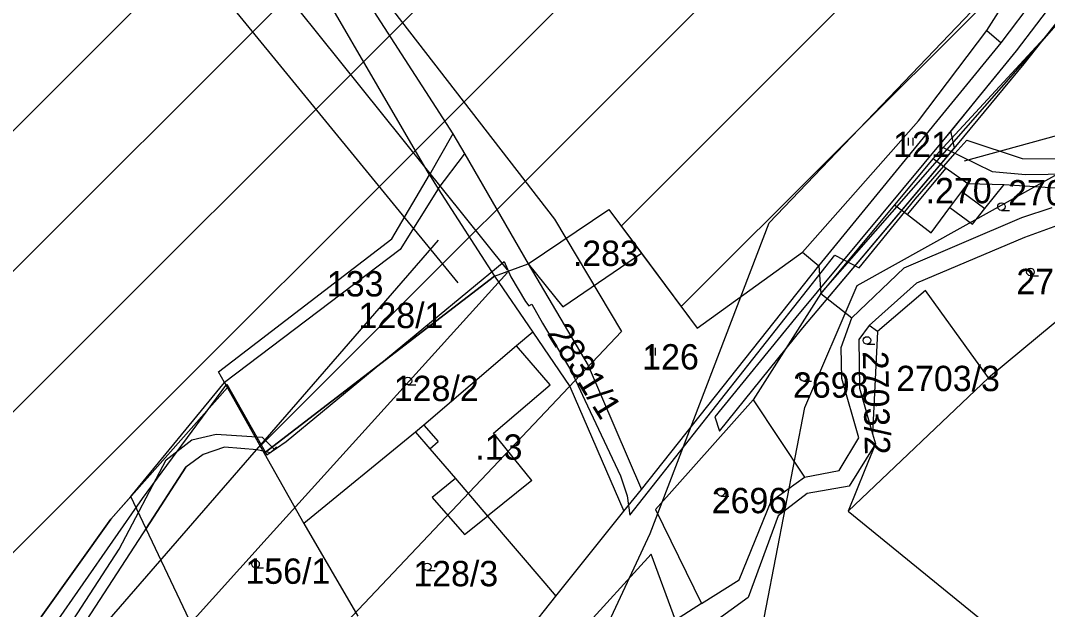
# Model space of a CAD drawing. Extents: x -564810 to -550519, y -1045831 to -1034011.
# Drawn here: x -552633.3 to -552426.8, y -1036239 to -1036120.6 of the extents above; entities that cross this region are included whole.
import ezdxf

# ---------------------------------------------------------------- set-up
doc = ezdxf.new("R2010")
doc.units = 0
for name, color, linetype in [('KN stav', 7, 'Continuous'), ('Obvod KPU', 7, 'Continuous'), ('Odvodněné plochy', 7, 'Continuous'), ('Parcelní čísla', 7, 'Continuous'), ('Polní cesty stavající', 7, 'Continuous'), ('přeložka st silnice', 7, 'Continuous'), ('STG', 7, 'Continuous'), ('Vedení VN', 7, 'Continuous'), ('vodní toky', 7, 'Continuous'), ('Vrstva 22', 7, 'Continuous'), ('Vrstva 33', 7, 'Continuous'), ('Vrstva 39', 7, 'Continuous'), ('Vrstva 4', 7, 'Continuous'), ('zamokř ploch', 7, 'Continuous')]:
    doc.layers.add(name, color=color, linetype=linetype)

msp = doc.modelspace()

# ---------------------------------------------------------------- linework, layer by layer
at = {"layer": 'KN stav'}
for p, q in [((-552439.04, -1036122.55), (-552415.84, -1036086.02)), ((-552436.15, -1036125.06), (-552407.92, -1036087.53)), ((-552551.05, -1036151.62), (-552585.7, -1036092.11)), ((-552562.25, -1036118.76), (-552546.35, -1036143.32)), ((-552425.11, -1036121.49), (-552447.79, -1036146.11)), ((-552452.79, -1036140.7), (-552439.04, -1036122.55)), ((-552439.04, -1036122.55), (-552436.15, -1036125.06)), ((-552472.81, -1036169.88), (-552436.15, -1036125.06)), ((-552476.07, -1036167.13), (-552452.79, -1036140.7)), ((-552546.35, -1036143.32), (-552551.05, -1036151.62)), ((-552546.35, -1036143.32), (-552543.98, -1036147.4)), ((-552447.79, -1036146.11), (-552449.83, -1036148.33)), ((-552447.79, -1036146.11), (-552437.97, -1036150.94)), ((-552543.98, -1036147.4), (-552531.19, -1036169.47)), ((-552449.83, -1036148.33), (-552457.56, -1036157.6)), ((-552449.83, -1036148.33), (-552447.18, -1036150.22)), ((-552447.18, -1036150.22), (-552442.87, -1036153.3)), ((-552558.64, -1036164.45), (-552551.05, -1036151.62)), ((-552551.05, -1036151.62), (-552549.34, -1036154.4)), ((-552437.97, -1036150.94), (-552431.25, -1036151.53)), ((-552431.25, -1036151.53), (-552397.93, -1036151.01)), ((-552549.34, -1036154.4), (-552556.92, -1036166.59)), ((-552549.34, -1036154.4), (-552537.97, -1036171.97)), ((-552442.87, -1036153.3), (-552435.51, -1036153.55)), ((-552439.4, -1036158.36), (-552435.51, -1036153.55)), ((-552435.51, -1036153.55), (-552414.02, -1036154.88)), ((-552531.19, -1036169.47), (-552514.99, -1036158.56)), ((-552514.99, -1036158.56), (-552508.46, -1036167.33)), ((-552457.56, -1036157.6), (-552472.42, -1036175.42)), ((-552457.56, -1036157.6), (-552454.98, -1036159.58)), ((-552450.2, -1036163.24), (-552446.44, -1036158.14)), ((-552446.44, -1036158.14), (-552441.92, -1036161.48)), ((-552441.92, -1036161.48), (-552439.4, -1036158.36)), ((-552431.96, -1036160.17), (-552425.89, -1036158.17)), ((-552455.66, -1036170.26), (-552431.96, -1036160.17)), ((-552454.98, -1036159.58), (-552450.2, -1036163.24)), ((-552424.82, -1036161.75), (-552431.48, -1036164.21)), ((-552593.47, -1036191.23), (-552558.64, -1036164.45)), ((-552431.48, -1036164.21), (-552453.15, -1036173.35)), ((-552556.92, -1036166.59), (-552592.25, -1036193.36)), ((-552524.26, -1036178.11), (-552508.46, -1036167.33)), ((-552508.46, -1036167.33), (-552497.23, -1036182.42)), ((-552497.23, -1036182.42), (-552476.07, -1036167.13)), ((-552476.07, -1036167.13), (-552472.81, -1036169.88)), ((-552531.19, -1036169.47), (-552519.16, -1036189.93)), ((-552531.19, -1036169.47), (-552524.26, -1036178.11)), ((-552508.44, -1036214.84), (-552472.81, -1036169.88)), ((-552466.14, -1036180.32), (-552455.66, -1036170.26)), ((-552537.97, -1036171.97), (-552584.28, -1036207.54)), ((-552537.97, -1036171.97), (-552530.3, -1036183.21)), ((-552453.15, -1036173.35), (-552462.67, -1036181.91)), ((-552472.42, -1036175.42), (-552485.97, -1036196.86)), ((-552472.42, -1036175.42), (-552466.14, -1036180.32)), ((-552451.34, -1036174.84), (-552460.98, -1036183.1)), ((-552440.44, -1036189.97), (-552451.34, -1036174.84)), ((-552418.79, -1036175.85), (-552438.69, -1036192.39)), ((-552468.32, -1036186.28), (-552466.14, -1036180.32)), ((-552530.3, -1036183.21), (-552533.54, -1036185.98)), ((-552530.3, -1036183.21), (-552522.86, -1036194.13)), ((-552462.67, -1036181.91), (-552464.76, -1036184.7)), ((-552460.98, -1036183.1), (-552462.67, -1036181.91)), ((-552460.98, -1036183.1), (-552461.99, -1036203.69)), ((-552533.54, -1036185.98), (-552552.17, -1036201.9)), ((-552464.76, -1036184.7), (-552464.61, -1036194.49)), ((-552468.18, -1036192.53), (-552468.32, -1036186.28)), ((-552519.16, -1036189.93), (-552508.44, -1036214.84)), ((-552438.69, -1036192.39), (-552440.44, -1036189.97)), ((-552592.25, -1036193.36), (-552593.47, -1036191.23)), ((-552611.08, -1036216.27), (-552592.25, -1036193.36)), ((-552592.25, -1036193.36), (-552584.28, -1036207.54)), ((-552522.86, -1036194.13), (-552511.96, -1036219.23)), ((-552464.76, -1036204.45), (-552468.18, -1036192.53)), ((-552438.69, -1036192.39), (-552466.93, -1036219.2)), ((-552464.61, -1036194.49), (-552461.99, -1036203.69)), ((-552485.97, -1036196.86), (-552505.62, -1036218.86)), ((-552485.97, -1036196.86), (-552475.68, -1036212.41)), ((-552552.17, -1036201.9), (-552553.84, -1036203.33)), ((-552553.84, -1036203.33), (-552576.32, -1036221.71)), ((-552553.84, -1036203.33), (-552550.99, -1036206.66)), ((-552468.69, -1036211.06), (-552464.76, -1036204.45)), ((-552461.99, -1036203.69), (-552461.43, -1036205.67)), ((-552550.99, -1036206.66), (-552545.84, -1036212.69)), ((-552461.43, -1036205.67), (-552466.68, -1036214.23)), ((-552461.43, -1036205.67), (-552463.55, -1036210.9)), ((-552584.28, -1036207.54), (-552576.32, -1036221.71)), ((-552545.84, -1036212.69), (-552550.5, -1036216.47)), ((-552482.37, -1036217.21), (-552475.68, -1036212.41)), ((-552475.68, -1036212.41), (-552468.69, -1036211.06)), ((-552463.55, -1036210.9), (-552466.93, -1036219.2)), ((-552511.96, -1036219.23), (-552508.44, -1036214.84)), ((-552466.68, -1036214.23), (-552475.14, -1036215.66)), ((-552611.08, -1036216.27), (-552615.12, -1036220.82)), ((-552591.56, -1036257.34), (-552611.08, -1036216.27)), ((-552550.5, -1036216.47), (-552544, -1036223.91)), ((-552475.14, -1036215.66), (-552480.94, -1036220.19)), ((-552505.62, -1036218.86), (-552496.35, -1036237.82)), ((-552488.78, -1036233.07), (-552482.37, -1036217.21)), ((-552615.12, -1036220.82), (-552629.11, -1036240.48)), ((-552544, -1036223.91), (-552539.4, -1036220.23)), ((-552539.4, -1036220.23), (-552527.88, -1036233.7)), ((-552525.64, -1036236.32), (-552511.96, -1036219.23)), ((-552480.94, -1036220.19), (-552486.98, -1036236.6)), ((-552466.93, -1036219.2), (-552429.76, -1036249.45)), ((-552576.32, -1036221.71), (-552565.44, -1036240.35)), ((-552506.51, -1036227.86), (-552529.69, -1036253.28)), ((-552501.62, -1036241.13), (-552506.51, -1036227.86)), ((-552496.35, -1036237.82), (-552488.78, -1036233.07)), ((-552527.88, -1036233.7), (-552525.64, -1036236.32)), ((-552549.35, -1036265.95), (-552525.64, -1036236.32)), ((-552486.98, -1036236.6), (-552493.81, -1036241.52)), ((-552496.35, -1036237.82), (-552501.62, -1036241.13))]:
    msp.add_line(p, q, dxfattribs=at)
at = {"layer": 'Obvod KPU'}
for p, q in [((-552445.46, -1036147.32), (-552443.06, -1036144.59)), ((-552443.06, -1036144.59), (-552431.9, -1036148.29)), ((-552453.42, -1036156.47), (-552445.46, -1036147.32)), ((-552431.9, -1036148.29), (-552396.09, -1036148.48)), ((-552464.67, -1036170.27), (-552453.42, -1036156.47)), ((-552579.83, -1036205.24), (-552536.04, -1036169.05)), ((-552536.04, -1036169.05), (-552534.69, -1036172.12)), ((-552510.78, -1036220), (-552469.56, -1036167.77)), ((-552469.56, -1036167.77), (-552464.67, -1036170.27)), ((-552534.69, -1036172.12), (-552531.73, -1036177.04)), ((-552531.73, -1036177.04), (-552531.1, -1036177.95)), ((-552531.1, -1036177.95), (-552530.49, -1036177.63)), ((-552530.49, -1036177.63), (-552528.35, -1036181.39)), ((-552528.35, -1036181.39), (-552522.51, -1036191.11)), ((-552522.51, -1036191.11), (-552519.84, -1036196.9)), ((-552608.73, -1036216.69), (-552591.76, -1036193.67)), ((-552591.76, -1036193.67), (-552583.76, -1036207.89)), ((-552519.84, -1036196.9), (-552512.64, -1036212.09)), ((-552583.76, -1036207.89), (-552579.83, -1036205.24)), ((-552512.64, -1036212.09), (-552511.33, -1036216.12)), ((-552626.64, -1036242.39), (-552608.73, -1036216.69)), ((-552511.33, -1036216.12), (-552510.78, -1036220))]:
    msp.add_line(p, q, dxfattribs=at)
at = {"layer": 'Odvodněné plochy'}
msp.add_lwpolyline([(-552771.59, -1036406.86), (-552722.24, -1036373.97), (-552691.61, -1036352.2), (-552668.59, -1036323.19), (-552652.27, -1036296.92), (-552629.11, -1036240.48), (-552615.12, -1036220.82), (-552615.12, -1036220.82), (-552591.66, -1036194.39), (-552584.28, -1036207.54), (-552537.97, -1036171.97), (-552531.19, -1036169.47), (-552514.99, -1036158.56), (-552497.23, -1036182.42), (-552476.07, -1036167.13), (-552472.81, -1036169.88), (-552472.42, -1036175.42), (-552425.11, -1036121.49)], dxfattribs=at)
at = {"layer": 'Polní cesty stavající'}
for p, q in [((-552421.46, -1036111.27), (-552433.1, -1036126.65)), ((-552431.52, -1036129.27), (-552418.1, -1036112.21)), ((-552433.1, -1036126.65), (-552440.88, -1036136.16)), ((-552444.95, -1036145.48), (-552431.52, -1036129.27)), ((-552440.89, -1036136.18), (-552446.29, -1036142.78)), ((-552440.87, -1036136.17), (-552440.89, -1036136.18)), ((-552440.88, -1036136.16), (-552440.87, -1036136.17)), ((-552447.39, -1036144.13), (-552477.41, -1036180.25)), ((-552446.29, -1036142.78), (-552447.39, -1036144.13)), ((-552445.55, -1036146.19), (-552446.29, -1036142.78)), ((-552476.03, -1036182.36), (-552445.55, -1036146.19)), ((-552445.55, -1036146.19), (-552444.95, -1036145.48)), ((-552445.55, -1036146.19), (-552445.55, -1036146.19)), ((-552477.41, -1036180.25), (-552493.69, -1036200.28)), ((-552492.77, -1036203.16), (-552476.03, -1036182.36)), ((-552493.69, -1036200.28), (-552492.77, -1036203.16))]:
    msp.add_line(p, q, dxfattribs=at)
at = {"layer": 'přeložka st silnice'}
for p, q in [((-553001.93, -1036509.87), (-552464.8, -1035972.74)), ((-552965.98, -1036502.2), (-552453.83, -1035990.05)), ((-552923.8, -1036488.3), (-552442.99, -1036007.49)), ((-552868.08, -1036460.87), (-552432.14, -1036024.93)), ((-552585.07, -1036206.14), (-552421.3, -1036042.38)), ((-552512.52, -1036161.88), (-552410.46, -1036059.82)), ((-552500.45, -1036178.09), (-552399.61, -1036077.26))]:
    msp.add_line(p, q, dxfattribs=at)
at = {"layer": 'STG'}
msp.add_lwpolyline([(-553913.89, -1037214.19), (-553796.31, -1037140.69), (-553706.3, -1037067.18), (-553629.14, -1036991.84), (-553566.68, -1036914.66), (-553476.66, -1036833.81), (-553318.67, -1036752.96), (-553234.16, -1036692.32), (-553142.31, -1036650.05), (-553048.61, -1036626.16), (-552953.09, -1036624.32), (-552903.48, -1036624.32), (-552861.23, -1036602.27), (-552798.77, -1036576.55), (-552738.15, -1036530.61), (-552646.29, -1036431.38), (-552581.99, -1036368.9), (-552545.25, -1036306.42), (-552506.67, -1036223.73), (-552482.79, -1036161.25), (-552440.54, -1036117.15)], dxfattribs=at)
at = {"layer": 'Vedení VN'}
msp.add_line((-552397.31, -1036136.11), (-552443.59, -1036148.81), dxfattribs=at)
for points in [[(-553567.53, -1034875.85), (-552617.75, -1036041.77), (-552525.91, -1036160.49), (-552512.48, -1036183.11), (-552698.29, -1036379.56), (-552912.35, -1036500.4), (-553117.93, -1036544.92), (-553344, -1036644.56), (-553507.2, -1036737.84), (-553648.49, -1036896.84), (-553694.41, -1037244.51), (-553658.38, -1037334.97)], [(-552545.26, -1036173.28), (-552777.69, -1035889.21), (-553252.44, -1035311.15), (-553606.39, -1034885.74)], [(-552535.38, -1036170.7), (-552615.17, -1036071.15), (-552694.28, -1035972.71), (-552775.29, -1035871.78), (-552858.09, -1035768.77), (-552941.67, -1035664.72), (-552998.64, -1035594.13), (-553079.78, -1035497.35), (-553163.27, -1035397.16), (-553257.3, -1035282.84), (-553335.17, -1035188.27), (-553563.62, -1034910.91)], [(-553684.52, -1037352.63), (-553725.5, -1037238.15), (-553666.15, -1036855.85), (-553493.77, -1036691.9), (-553319.98, -1036604.98), (-553120.76, -1036515.94), (-552942.02, -1036478.49), (-552709.59, -1036345.64), (-552689.1, -1036325.85), (-552549.22, -1036164.73)], [(-552535.38, -1036171.2), (-552583.65, -1036224.68), (-552638.09, -1036285.01), (-552707.08, -1036361.35), (-552775.22, -1036401.6), (-552849.05, -1036445.27), (-552919.03, -1036487.18), (-553014.59, -1036507.93)]]:
    msp.add_lwpolyline(points, dxfattribs=at)
at = {"layer": 'vodní toky'}
for p, q in [((-552598.82, -1036204.89), (-552593.95, -1036203.74)), ((-552593.95, -1036203.74), (-552584.68, -1036204.37)), ((-552584.68, -1036204.37), (-552582.26, -1036206.78)), ((-552604, -1036208.91), (-552598.82, -1036204.89)), ((-552592.28, -1036206.34), (-552596.54, -1036207.86)), ((-552585.7, -1036206.88), (-552592.28, -1036206.34)), ((-552581.83, -1036206.28), (-552582.26, -1036206.78)), ((-552596.54, -1036207.86), (-552600.06, -1036210.37)), ((-552583.11, -1036207.5), (-552585.7, -1036206.88)), ((-552582.26, -1036206.78), (-552583.11, -1036207.5)), ((-552600.06, -1036210.37), (-552643.98, -1036278.13)), ((-552613.4, -1036226.85), (-552604, -1036208.91)), ((-552600.06, -1036210.37), (-552608.03, -1036222.7)), ((-552608.03, -1036222.7), (-552600.06, -1036210.37)), ((-552631.77, -1036255.01), (-552613.4, -1036226.85))]:
    msp.add_line(p, q, dxfattribs=at)
at = {"layer": 'Vrstva 33'}
msp.add_lwpolyline([(-552487.9, -1036311.48), (-552487.24, -1036258.74), (-552475.61, -1036198.41), (-552465.08, -1036173.84), (-552407.68, -1036141.86), (-552378.62, -1036137.49), (-552358.27, -1036118.6), (-552372.08, -1036090.97), (-552401.14, -1036077.89), (-552462.9, -1036072.08), (-552521.02, -1036078.62), (-552548.63, -1036095.34), (-552579.87, -1036114.96)], dxfattribs=at)
at = {"layer": 'Vrstva 39'}
for p, q in [((-552421.46, -1036111.27), (-552433.1, -1036126.65)), ((-552431.52, -1036129.27), (-552418.1, -1036112.21)), ((-552433.1, -1036126.65), (-552447.39, -1036144.13)), ((-552444.95, -1036145.48), (-552431.52, -1036129.27)), ((-552476.03, -1036182.36), (-552444.95, -1036145.48)), ((-552477.41, -1036180.25), (-552493.69, -1036200.28)), ((-552477.41, -1036180.25), (-552477.41, -1036180.25)), ((-552492.77, -1036203.16), (-552476.03, -1036182.36)), ((-552493.69, -1036200.28), (-552492.77, -1036203.16)), ((-552493.69, -1036200.28), (-552492.77, -1036203.16))]:
    msp.add_line(p, q, dxfattribs=at)
at = {"layer": 'Vrstva 4'}
for p, q in [((-552549.34, -1036154.4), (-552543.99, -1036147.4)), ((-552454.98, -1036159.58), (-552447.18, -1036150.22)), ((-552446.44, -1036158.14), (-552444.07, -1036154.92)), ((-552444.07, -1036154.92), (-552442.87, -1036153.3)), ((-552444.07, -1036154.92), (-552439.4, -1036158.36)), ((-552526.83, -1036193.82), (-552533.54, -1036185.98)), ((-552538.2, -1036203.54), (-552526.83, -1036193.82)), ((-552552.17, -1036201.9), (-552549.32, -1036205.23)), ((-552530.45, -1036213.06), (-552538.2, -1036203.54)), ((-552550.99, -1036206.66), (-552549.32, -1036205.23)), ((-552545.84, -1036212.69), (-552539.4, -1036220.22)), ((-552530.45, -1036213.06), (-552539.4, -1036220.22))]:
    msp.add_line(p, q, dxfattribs=at)
at = {"layer": 'zamokř ploch'}
for p, q in [((-552454.87, -1036144.16), (-552454.87, -1036145.66)), ((-552453.87, -1036144.16), (-552453.87, -1036145.66)), ((-552436.09, -1036158.73), (-552434.49, -1036158.73)), ((-552430.27, -1036171.87), (-552428.67, -1036171.87)), ((-552463.12, -1036185.64), (-552461.52, -1036185.64)), ((-552506.72, -1036186.4), (-552506.72, -1036187.9)), ((-552505.72, -1036186.4), (-552505.72, -1036187.9)), ((-552555.38, -1036193.79), (-552553.78, -1036193.79)), ((-552475.85, -1036193.05), (-552474.25, -1036193.05)), ((-552492.46, -1036216.18), (-552490.86, -1036216.18)), ((-552586.01, -1036230.62), (-552584.41, -1036230.62)), ((-552551.5, -1036231.17), (-552549.9, -1036231.17))]:
    msp.add_line(p, q, dxfattribs=at)
for centre in [(-552436.09, -1036157.98), (-552430.27, -1036171.12), (-552463.12, -1036184.89), (-552475.85, -1036192.3), (-552555.38, -1036193.04), (-552492.46, -1036215.43), (-552586.01, -1036229.87), (-552551.5, -1036230.42)]:
    msp.add_circle(centre, 0.75, dxfattribs=at)

# ---------------------------------------------------------------- texts
at = {"layer": 'Parcelní čísla'}
for s, p in [('121', (-552457.84, -1036148.03)), ('2700/1', (-552434.74, -1036157.74)), ('133', (-552571.68, -1036176.05)), ('2703/1', (-552433.09, -1036175.59)), ('128/1', (-552565.32, -1036182.41)), ('126', (-552508.29, -1036190.74)), ('2703/3', (-552457.25, -1036195.09)), ('128/2', (-552558.23, -1036197.1)), ('2698', (-552477.99, -1036196.41)), ('2696', (-552494.32, -1036219.64)), ('156/1', (-552588.06, -1036233.84)), ('128/3', (-552554.31, -1036234.33))]:
    msp.add_text(s, height=5.1, dxfattribs=at).set_placement(p)
for s, rotation, p in [('2831/1', 301.8164, (-552527.54, -1036183.44)), ('2703/2', 271.237, (-552463.97, -1036187.06))]:
    msp.add_text(s, height=5.1, rotation=rotation, dxfattribs=at).set_placement(p)
at = {"layer": 'Vrstva 22'}
for s, p in [('.270', (-552451.33, -1036157.31)), ('.283', (-552522.24, -1036169.92)), ('.13', (-552541.85, -1036208.89))]:
    msp.add_text(s, height=5.1, dxfattribs=at).set_placement(p)

doc.saveas('drawing.dxf')
